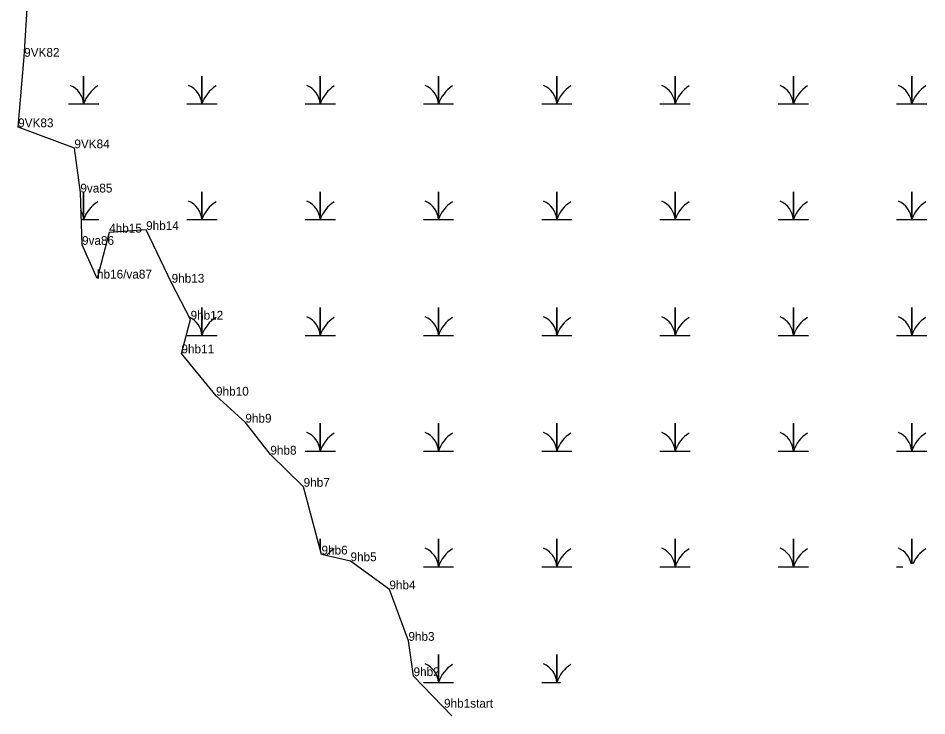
# Model space of a CAD drawing. Extents: x 2072529 to 2268796, y 436423 to 470397.
# Drawn here: x 2205507 to 2206024, y 446974 to 447371 of the extents above; entities that cross this region are included whole.
import ezdxf

# ---------------------------------------------------------------- set-up
doc = ezdxf.new("R2010")
doc.units = 0
for name, color, linetype in [('Exist Environmental Wetland Boundary', 7, 'Continuous'), ('Exist Environmental Wetland Boundary Cogo Comment', 7, 'Continuous'), ('Exist Environmental Wetland Boundary Cogo Point CELL', 7, 'Continuous'), ('Exist Hydro Swamp or Marsh', 7, 'Continuous')]:
    doc.layers.add(name, color=color, linetype=linetype)

msp = doc.modelspace()

# ---------------------------------------------------------------- linework, layer by layer
at = {"layer": 'Exist Environmental Wetland Boundary'}
for points in [[(2205552.17, 447223.17), (2205543.65, 447242.35), (2205542.7, 447272.12), (2205539.3, 447297.26), (2205507.35, 447309.23), (2205510.77, 447349.31), (2205512.65, 447379.36)], [(2205753.91, 446974.47), (2205732.12, 446997.05), (2205729.21, 447017.14), (2205718.39, 447046.41), (2205696.29, 447062.42), (2205679.8, 447066.23), (2205669.63, 447104.75), (2205650.73, 447123.04), (2205636.51, 447141.22), (2205619.85, 447156.56), (2205600.18, 447180.63), (2205605.35, 447199.81), (2205594.59, 447220.82), (2205580.1, 447250.8), (2205559.08, 447249.3), (2205552.17, 447223.17)]]:
    msp.add_lwpolyline(points, dxfattribs=at)
at = {"layer": 'Exist Environmental Wetland Boundary Cogo Point CELL'}
for p, q in [((2205510.77, 447349.31), (2205510.77, 447349.31)), ((2205507.35, 447309.23), (2205507.35, 447309.23)), ((2205539.3, 447297.26), (2205539.3, 447297.26)), ((2205542.7, 447272.12), (2205542.7, 447272.12)), ((2205542.7, 447272.12), (2205542.7, 447272.12)), ((2205559.08, 447249.3), (2205559.08, 447249.3)), ((2205559.08, 447249.3), (2205559.08, 447249.3)), ((2205580.1, 447250.8), (2205580.1, 447250.8)), ((2205580.1, 447250.8), (2205580.1, 447250.8)), ((2205543.65, 447242.35), (2205543.65, 447242.35)), ((2205543.65, 447242.35), (2205543.65, 447242.35)), ((2205552.17, 447223.17), (2205552.17, 447223.17)), ((2205552.17, 447223.17), (2205552.17, 447223.17)), ((2205594.59, 447220.82), (2205594.59, 447220.82)), ((2205594.59, 447220.82), (2205594.59, 447220.82)), ((2205605.35, 447199.81), (2205605.35, 447199.81)), ((2205605.35, 447199.81), (2205605.35, 447199.81)), ((2205600.18, 447180.63), (2205600.18, 447180.63)), ((2205600.18, 447180.63), (2205600.18, 447180.63)), ((2205619.85, 447156.56), (2205619.85, 447156.56)), ((2205619.85, 447156.56), (2205619.85, 447156.56)), ((2205636.51, 447141.22), (2205636.51, 447141.22)), ((2205636.51, 447141.22), (2205636.51, 447141.22)), ((2205650.73, 447123.04), (2205650.73, 447123.04)), ((2205650.73, 447123.04), (2205650.73, 447123.04)), ((2205669.63, 447104.75), (2205669.63, 447104.75)), ((2205669.63, 447104.75), (2205669.63, 447104.75)), ((2205679.8, 447066.23), (2205679.8, 447066.23)), ((2205679.8, 447066.23), (2205679.8, 447066.23)), ((2205696.29, 447062.42), (2205696.29, 447062.42)), ((2205696.29, 447062.42), (2205696.29, 447062.42)), ((2205718.39, 447046.41), (2205718.39, 447046.41)), ((2205718.39, 447046.41), (2205718.39, 447046.41)), ((2205729.21, 447017.14), (2205729.21, 447017.14)), ((2205729.21, 447017.14), (2205729.21, 447017.14)), ((2205732.12, 446997.05), (2205732.12, 446997.05)), ((2205732.12, 446997.05), (2205732.12, 446997.05)), ((2205749.44, 446979.1), (2205749.44, 446979.1)), ((2205749.44, 446979.1), (2205749.44, 446979.1))]:
    msp.add_line(p, q, dxfattribs=at)
at = {"layer": 'Exist Hydro Swamp or Marsh'}
for points in [[(2205535.97, 447322.48), (2205544.57, 447322.48), (2205544.57, 447338.27), (2205544.57, 447322.48), (2205553.17, 447322.48)], [(2205603.22, 447322.48), (2205611.82, 447322.48), (2205611.82, 447338.27), (2205611.82, 447322.48), (2205620.42, 447322.48)], [(2205670.47, 447322.48), (2205679.07, 447322.48), (2205679.07, 447338.27), (2205679.07, 447322.48), (2205687.67, 447322.48)], [(2205737.72, 447322.48), (2205746.32, 447322.48), (2205746.32, 447338.27), (2205746.32, 447322.48), (2205754.92, 447322.48)], [(2205804.97, 447322.48), (2205813.57, 447322.48), (2205813.57, 447338.27), (2205813.57, 447322.48), (2205822.17, 447322.48)], [(2205872.22, 447322.48), (2205880.82, 447322.48), (2205880.82, 447338.27), (2205880.82, 447322.48), (2205889.42, 447322.48)], [(2205939.47, 447322.48), (2205948.07, 447322.48), (2205948.07, 447338.27), (2205948.07, 447322.48), (2205956.67, 447322.48)], [(2206006.72, 447322.48), (2206015.32, 447322.48), (2206015.32, 447338.27), (2206015.32, 447322.48), (2206023.92, 447322.48)], [(2205543.19, 447256.68), (2205544.57, 447256.68), (2205544.57, 447272.47), (2205544.57, 447256.68), (2205553.17, 447256.68)], [(2205603.22, 447256.68), (2205611.82, 447256.68), (2205611.82, 447272.47), (2205611.82, 447256.68), (2205620.42, 447256.68)], [(2205670.47, 447256.68), (2205679.07, 447256.68), (2205679.07, 447272.47), (2205679.07, 447256.68), (2205687.67, 447256.68)], [(2205737.72, 447256.68), (2205746.32, 447256.68), (2205746.32, 447272.47), (2205746.32, 447256.68), (2205754.92, 447256.68)], [(2205804.97, 447256.68), (2205813.57, 447256.68), (2205813.57, 447272.47), (2205813.57, 447256.68), (2205822.17, 447256.68)], [(2205872.22, 447256.68), (2205880.82, 447256.68), (2205880.82, 447272.47), (2205880.82, 447256.68), (2205889.42, 447256.68)], [(2205939.47, 447256.68), (2205948.07, 447256.68), (2205948.07, 447272.47), (2205948.07, 447256.68), (2205956.67, 447256.68)], [(2206006.72, 447256.68), (2206015.32, 447256.68), (2206015.32, 447272.47), (2206015.32, 447256.68), (2206023.92, 447256.68)], [(2205603.22, 447190.88), (2205611.82, 447190.88), (2205611.82, 447206.67), (2205611.82, 447190.88), (2205620.42, 447190.88)], [(2205670.47, 447190.88), (2205679.07, 447190.88), (2205679.07, 447206.67), (2205679.07, 447190.88), (2205687.67, 447190.88)], [(2205737.72, 447190.88), (2205746.32, 447190.88), (2205746.32, 447206.67), (2205746.32, 447190.88), (2205754.92, 447190.88)], [(2205804.97, 447190.88), (2205813.57, 447190.88), (2205813.57, 447206.67), (2205813.57, 447190.88), (2205822.17, 447190.88)], [(2205872.22, 447190.88), (2205880.82, 447190.88), (2205880.82, 447206.67), (2205880.82, 447190.88), (2205889.42, 447190.88)], [(2205939.47, 447190.88), (2205948.07, 447190.88), (2205948.07, 447206.67), (2205948.07, 447190.88), (2205956.67, 447190.88)], [(2206006.72, 447190.88), (2206015.32, 447190.88), (2206015.32, 447206.67), (2206015.32, 447190.88), (2206023.92, 447190.88)], [(2205670.47, 447125.08), (2205679.07, 447125.08), (2205679.07, 447140.87), (2205679.07, 447125.08), (2205687.67, 447125.08)], [(2205737.72, 447125.08), (2205746.32, 447125.08), (2205746.32, 447140.87), (2205746.32, 447125.08), (2205754.92, 447125.08)], [(2205804.97, 447125.08), (2205813.57, 447125.08), (2205813.57, 447140.87), (2205813.57, 447125.08), (2205822.17, 447125.08)], [(2205872.22, 447125.08), (2205880.82, 447125.08), (2205880.82, 447140.87), (2205880.82, 447125.08), (2205889.42, 447125.08)], [(2205939.47, 447125.08), (2205948.07, 447125.08), (2205948.07, 447140.87), (2205948.07, 447125.08), (2205956.67, 447125.08)], [(2206006.72, 447125.08), (2206015.32, 447125.08), (2206015.32, 447140.87), (2206015.32, 447125.08), (2206023.92, 447125.08)], [(2205679.07, 447069), (2205679.07, 447075.07), (2205679.07, 447069)], [(2205737.72, 447059.28), (2205746.32, 447059.28), (2205746.32, 447075.07), (2205746.32, 447059.28), (2205754.92, 447059.28)], [(2205804.97, 447059.28), (2205813.57, 447059.28), (2205813.57, 447075.07), (2205813.57, 447059.28), (2205822.17, 447059.28)], [(2205872.22, 447059.28), (2205880.82, 447059.28), (2205880.82, 447075.07), (2205880.82, 447059.28), (2205889.42, 447059.28)], [(2205939.47, 447059.28), (2205948.07, 447059.28), (2205948.07, 447075.07), (2205948.07, 447059.28), (2205956.67, 447059.28)], [(2206015.32, 447060.85), (2206015.32, 447075.07), (2206015.32, 447060.85)], [(2206006.72, 447059.28), (2206010.36, 447059.28)], [(2205737.72, 446993.48), (2205746.32, 446993.48), (2205746.32, 447009.27), (2205746.32, 446993.48), (2205754.92, 446993.48)], [(2205804.97, 446993.48), (2205813.57, 446993.48), (2205813.57, 447009.27), (2205813.57, 446993.48), (2205815.68, 446993.48)]]:
    msp.add_lwpolyline(points, dxfattribs=at)
for centre, radius, start, end in [((2205532.3, 447321.6), 12.3, 4.1403, 67.535), ((2205562.81, 447316.42), 19.22, 122.1274, 161.6222), ((2205599.55, 447321.6), 12.3, 4.1403, 67.535), ((2205630.06, 447316.42), 19.22, 122.1274, 161.6222), ((2205666.8, 447321.6), 12.3, 4.1403, 67.535), ((2205697.31, 447316.42), 19.22, 122.1274, 161.6222), ((2205734.05, 447321.6), 12.3, 4.1403, 67.535), ((2205764.56, 447316.42), 19.22, 122.1274, 161.6222), ((2205801.3, 447321.6), 12.3, 4.1403, 67.535), ((2205831.81, 447316.42), 19.22, 122.1274, 161.6222), ((2205868.55, 447321.6), 12.3, 4.1403, 67.535), ((2205899.06, 447316.42), 19.22, 122.1274, 161.6222), ((2205935.8, 447321.6), 12.3, 4.1403, 67.535), ((2205966.31, 447316.42), 19.22, 122.1274, 161.6222), ((2206003.05, 447321.6), 12.3, 4.1403, 67.535), ((2206033.56, 447316.42), 19.22, 122.1274, 161.6222), ((2205562.81, 447250.62), 19.22, 122.1274, 161.6222), ((2205599.55, 447255.8), 12.3, 4.1403, 67.535), ((2205630.06, 447250.62), 19.22, 122.1274, 161.6222), ((2205666.8, 447255.8), 12.3, 4.1403, 67.535), ((2205697.31, 447250.62), 19.22, 122.1274, 161.6222), ((2205734.05, 447255.8), 12.3, 4.1403, 67.535), ((2205764.56, 447250.62), 19.22, 122.1274, 161.6222), ((2205801.3, 447255.8), 12.3, 4.1403, 67.535), ((2205831.81, 447250.62), 19.22, 122.1274, 161.6222), ((2205868.55, 447255.8), 12.3, 4.1403, 67.535), ((2205899.06, 447250.62), 19.22, 122.1274, 161.6222), ((2205935.8, 447255.8), 12.3, 4.1403, 67.535), ((2205966.31, 447250.62), 19.22, 122.1274, 161.6222), ((2206003.05, 447255.8), 12.3, 4.1403, 67.535), ((2206033.56, 447250.62), 19.22, 122.1274, 161.6222), ((2205532.3, 447255.8), 12.3, 4.1403, 29.2758), ((2205599.55, 447190), 12.3, 4.1403, 65.5524), ((2205630.06, 447184.82), 19.22, 122.1274, 161.6222), ((2205666.8, 447190), 12.3, 4.1403, 67.535), ((2205697.31, 447184.82), 19.22, 122.1274, 161.6222), ((2205734.05, 447190), 12.3, 4.1403, 67.535), ((2205764.56, 447184.82), 19.22, 122.1274, 161.6222), ((2205801.3, 447190), 12.3, 4.1403, 67.535), ((2205831.81, 447184.82), 19.22, 122.1274, 161.6222), ((2205868.55, 447190), 12.3, 4.1403, 67.535), ((2205899.06, 447184.82), 19.22, 122.1274, 161.6222), ((2205935.8, 447190), 12.3, 4.1403, 67.535), ((2205966.31, 447184.82), 19.22, 122.1274, 161.6222), ((2206003.05, 447190), 12.3, 4.1403, 67.535), ((2206033.56, 447184.82), 19.22, 122.1274, 161.6222), ((2205666.8, 447124.2), 12.3, 4.1403, 67.535), ((2205697.31, 447119.02), 19.22, 122.1274, 161.6222), ((2205734.05, 447124.2), 12.3, 4.1403, 67.535), ((2205764.56, 447119.02), 19.22, 122.1274, 161.6222), ((2205801.3, 447124.2), 12.3, 4.1403, 67.535), ((2205831.81, 447119.02), 19.22, 122.1274, 161.6222), ((2205868.55, 447124.2), 12.3, 4.1403, 67.535), ((2205899.06, 447119.02), 19.22, 122.1274, 161.6222), ((2205935.8, 447124.2), 12.3, 4.1403, 67.535), ((2205966.31, 447119.02), 19.22, 122.1274, 161.6222), ((2206003.05, 447124.2), 12.3, 4.1403, 67.535), ((2206033.56, 447119.02), 19.22, 122.1274, 161.6222), ((2205697.31, 447053.22), 19.22, 122.1274, 139.9771), ((2205734.05, 447058.4), 12.3, 4.1403, 67.535), ((2205764.56, 447053.22), 19.22, 122.1274, 161.6222), ((2205801.3, 447058.4), 12.3, 4.1403, 67.535), ((2205831.81, 447053.22), 19.22, 122.1274, 161.6222), ((2205868.55, 447058.4), 12.3, 4.1403, 67.535), ((2205899.06, 447053.22), 19.22, 122.1274, 161.6222), ((2205935.8, 447058.4), 12.3, 4.1403, 67.535), ((2205966.31, 447053.22), 19.22, 122.1274, 161.6222), ((2206003.05, 447058.4), 12.3, 11.2135, 67.535), ((2206033.56, 447053.22), 19.22, 122.1274, 155.9041), ((2205734.05, 446992.6), 12.3, 4.1403, 67.535), ((2205764.56, 446987.42), 19.22, 122.1274, 161.6222), ((2205801.3, 446992.6), 12.3, 4.1403, 67.535), ((2205831.81, 446987.42), 19.22, 122.1274, 161.6222)]:
    msp.add_arc(centre, radius, start, end, dxfattribs=at)

# ---------------------------------------------------------------- texts
at = {"layer": 'Exist Environmental Wetland Boundary Cogo Comment'}
for s, p in [('9VK82', (2205510.77, 447349.31)), ('9VK83', (2205507.35, 447309.23)), ('9VK84', (2205539.3, 447297.26)), ('9va85', (2205542.7, 447272.12)), ('4hb15', (2205559.08, 447249.3)), ('9hb14', (2205580.1, 447250.8)), ('9va86', (2205543.65, 447242.35)), ('hb16/va87', (2205552.17, 447223.17)), ('9hb13', (2205594.59, 447220.82)), ('9hb12', (2205605.35, 447199.81)), ('9hb11', (2205600.18, 447180.63)), ('9hb10', (2205619.85, 447156.56)), ('9hb9', (2205636.51, 447141.22)), ('9hb8', (2205650.73, 447123.04)), ('9hb7', (2205669.63, 447104.75)), ('9hb6', (2205679.8, 447066.23)), ('9hb5', (2205696.29, 447062.42)), ('9hb4', (2205718.39, 447046.41)), ('9hb3', (2205729.21, 447017.14)), ('9hb2', (2205732.12, 446997.05)), ('9hb1start', (2205749.44, 446979.1))]:
    msp.add_text(s, height=5, dxfattribs=at).set_placement(p)

doc.saveas('drawing.dxf')
